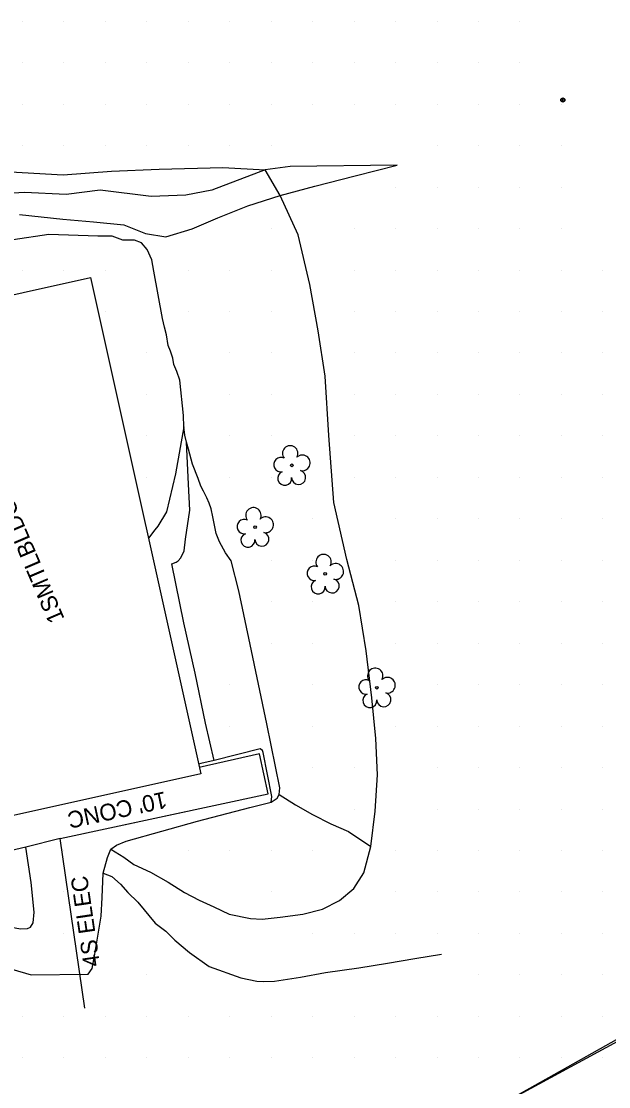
# Model space of a CAD drawing. Extents: x 1548934 to 1561348, y 809680 to 824075.
# Drawn here: x 1551789.7 to 1551931.4, y 811053 to 811310 of the extents above; entities that cross this region are included whole.
import ezdxf

# ---------------------------------------------------------------- set-up
doc = ezdxf.new("R2010")
doc.units = 0
for name, color, linetype in [('Default', 7, 'Continuous'), ('Exist Building', 7, 'Continuous'), ('Exist Building Foundations Text', 7, 'Continuous'), ('Exist DTM QL2 LIDAR Elevation Point', 7, 'Continuous'), ('Exist Other Culture Area Outline', 7, 'Continuous'), ('Exist Other Culture Area Outline Text', 7, 'Continuous'), ('Exist Other Culture Fence Line Text', 7, 'Continuous'), ('Exist Roads Soil', 7, 'Continuous'), ('Exist Vegetation Tree CELL', 7, 'Continuous'), ('Exist Vegetation Woods Line', 7, 'Continuous'), ('P_RDY_Dimension_Text', 7, 'Continuous'), ('PH Exist DTM Breakline', 7, 'Continuous')]:
    doc.layers.add(name, color=color, linetype=linetype)

# ---------------------------------------------------------------- blocks, each defined once
blk = doc.blocks.new('SurveyPointCell')
at = {"layer": 'Default'}
for p, q in [((-0.5, 0), (0.5, 0)), ((0, -0.5), (0, 0.5))]:
    blk.add_line(p, q, dxfattribs=at)
blk.add_circle((0, 0), 0.5, dxfattribs=at)

msp = doc.modelspace()

# ---------------------------------------------------------------- linework, layer by layer
at = {"layer": 'Exist Building'}
msp.add_lwpolyline([(1551783.41, 811117.5), (1551756.83, 811237.21), (1551806.41, 811248.22), (1551832.98, 811128.51)], close=True, dxfattribs=at)
at = {"layer": 'Exist DTM QL2 LIDAR Elevation Point'}
for p, q in [((1551790, 811310.04), (1551790, 811310.04)), ((1551800, 811310.04), (1551800, 811310.04)), ((1551810, 811310.04), (1551810, 811310.04)), ((1551820, 811310.04), (1551820, 811310.04)), ((1551830.01, 811310.04), (1551830.01, 811310.04)), ((1551840.01, 811310.04), (1551840.01, 811310.04)), ((1551850.01, 811310.04), (1551850.01, 811310.04)), ((1551860.01, 811310.04), (1551860.01, 811310.04)), ((1551870.01, 811310.04), (1551870.01, 811310.04)), ((1551880.01, 811310.04), (1551880.01, 811310.04)), ((1551890.01, 811310.04), (1551890.01, 811310.04)), ((1551900.01, 811310.04), (1551900.01, 811310.04)), ((1551910.01, 811310.04), (1551910.01, 811310.04)), ((1551790, 811300.03), (1551790, 811300.03)), ((1551800, 811300.03), (1551800, 811300.03)), ((1551810, 811300.03), (1551810, 811300.03)), ((1551820, 811300.03), (1551820, 811300.03)), ((1551830.01, 811300.03), (1551830.01, 811300.03)), ((1551840.01, 811300.03), (1551840.01, 811300.03)), ((1551850.01, 811300.03), (1551850.01, 811300.03)), ((1551860.01, 811300.03), (1551860.01, 811300.03)), ((1551870.01, 811300.03), (1551870.01, 811300.03)), ((1551880.01, 811300.03), (1551880.01, 811300.03)), ((1551890.01, 811300.03), (1551890.01, 811300.03)), ((1551900.01, 811300.03), (1551900.01, 811300.03)), ((1551910.01, 811300.03), (1551910.01, 811300.03)), ((1551790, 811290.03), (1551790, 811290.03)), ((1551800, 811290.03), (1551800, 811290.03)), ((1551810, 811290.03), (1551810, 811290.03)), ((1551820, 811290.03), (1551820, 811290.03)), ((1551830.01, 811290.03), (1551830.01, 811290.03)), ((1551840.01, 811290.03), (1551840.01, 811290.03)), ((1551850.01, 811290.03), (1551850.01, 811290.03)), ((1551860.01, 811290.03), (1551860.01, 811290.03)), ((1551870.01, 811290.03), (1551870.01, 811290.03)), ((1551880.01, 811290.03), (1551880.01, 811290.03)), ((1551890.01, 811290.03), (1551890.01, 811290.03)), ((1551900.01, 811290.03), (1551900.01, 811290.03)), ((1551910.01, 811290.03), (1551910.01, 811290.03)), ((1551920.01, 811290.03), (1551920.01, 811290.03)), ((1551790, 811280.03), (1551790, 811280.03)), ((1551800, 811280.03), (1551800, 811280.03)), ((1551810, 811280.03), (1551810, 811280.03)), ((1551820, 811280.03), (1551820, 811280.03)), ((1551830.01, 811280.03), (1551830.01, 811280.03)), ((1551840.01, 811280.03), (1551840.01, 811280.03)), ((1551850.01, 811280.03), (1551850.01, 811280.03)), ((1551890.01, 811280.03), (1551890.01, 811280.03)), ((1551900.01, 811280.03), (1551900.01, 811280.03)), ((1551910.01, 811280.03), (1551910.01, 811280.03)), ((1551920.01, 811280.03), (1551920.01, 811280.03)), ((1551880.01, 811270.03), (1551880.01, 811270.03)), ((1551890.01, 811270.03), (1551890.01, 811270.03)), ((1551900.01, 811270.03), (1551900.01, 811270.03)), ((1551910.01, 811270.03), (1551910.01, 811270.03)), ((1551920.01, 811270.03), (1551920.01, 811270.03)), ((1551850.01, 811260.03), (1551850.01, 811260.03)), ((1551870.01, 811260.03), (1551870.01, 811260.03)), ((1551880.01, 811260.03), (1551880.01, 811260.03)), ((1551890.01, 811260.03), (1551890.01, 811260.03)), ((1551900.01, 811260.03), (1551900.01, 811260.03)), ((1551910.01, 811260.03), (1551910.01, 811260.03)), ((1551920.01, 811260.03), (1551920.01, 811260.03)), ((1551790, 811250.03), (1551790, 811250.03)), ((1551800, 811250.03), (1551800, 811250.03)), ((1551810, 811250.03), (1551810, 811250.03)), ((1551830.01, 811250.03), (1551830.01, 811250.03)), ((1551840.01, 811250.03), (1551840.01, 811250.03)), ((1551850.01, 811250.03), (1551850.01, 811250.03)), ((1551870.01, 811250.03), (1551870.01, 811250.03)), ((1551880.01, 811250.03), (1551880.01, 811250.03)), ((1551890.01, 811250.03), (1551890.01, 811250.03)), ((1551900.01, 811250.03), (1551900.01, 811250.03)), ((1551910.01, 811250.03), (1551910.01, 811250.03)), ((1551920.01, 811250.03), (1551920.01, 811250.03)), ((1551930.01, 811250.03), (1551930.01, 811250.03)), ((1551810, 811240.03), (1551810, 811240.03)), ((1551830.01, 811240.03), (1551830.01, 811240.03)), ((1551840.01, 811240.03), (1551840.01, 811240.03)), ((1551850.01, 811240.03), (1551850.01, 811240.03)), ((1551870.01, 811240.03), (1551870.01, 811240.03)), ((1551880.01, 811240.03), (1551880.01, 811240.03)), ((1551890.01, 811240.03), (1551890.01, 811240.03)), ((1551900.01, 811240.03), (1551900.01, 811240.03)), ((1551910.01, 811240.03), (1551910.01, 811240.03)), ((1551920.01, 811240.03), (1551920.01, 811240.03)), ((1551930.01, 811240.03), (1551930.01, 811240.03)), ((1551820, 811230.03), (1551820, 811230.03)), ((1551840.01, 811230.03), (1551840.01, 811230.03)), ((1551850.01, 811230.03), (1551850.01, 811230.03)), ((1551870.01, 811230.03), (1551870.01, 811230.03)), ((1551880.01, 811230.03), (1551880.01, 811230.03)), ((1551890.01, 811230.03), (1551890.01, 811230.03)), ((1551900.01, 811230.03), (1551900.01, 811230.03)), ((1551910.01, 811230.03), (1551910.01, 811230.03)), ((1551920.01, 811230.03), (1551920.01, 811230.03)), ((1551930.01, 811230.03), (1551930.01, 811230.03)), ((1551820, 811220.03), (1551820, 811220.03)), ((1551840.01, 811220.03), (1551840.01, 811220.03)), ((1551850.01, 811220.03), (1551850.01, 811220.03)), ((1551870.01, 811220.03), (1551870.01, 811220.03)), ((1551880.01, 811220.03), (1551880.01, 811220.03)), ((1551890.01, 811220.03), (1551890.01, 811220.03)), ((1551900.01, 811220.03), (1551900.01, 811220.03)), ((1551910.01, 811220.03), (1551910.01, 811220.03)), ((1551920.01, 811220.03), (1551920.01, 811220.03)), ((1551930.01, 811220.03), (1551930.01, 811220.03)), ((1551820, 811210.03), (1551820, 811210.03)), ((1551840.01, 811210.03), (1551840.01, 811210.03)), ((1551850.01, 811210.03), (1551850.01, 811210.03)), ((1551870.01, 811210.03), (1551870.01, 811210.03)), ((1551880.01, 811210.03), (1551880.01, 811210.03)), ((1551890.01, 811210.03), (1551890.01, 811210.03)), ((1551900.01, 811210.03), (1551900.01, 811210.03)), ((1551910.01, 811210.03), (1551910.01, 811210.03)), ((1551920.01, 811210.03), (1551920.01, 811210.03)), ((1551930.01, 811210.03), (1551930.01, 811210.03)), ((1551820, 811200.03), (1551820, 811200.03)), ((1551840.01, 811200.03), (1551840.01, 811200.03)), ((1551850.01, 811200.03), (1551850.01, 811200.03)), ((1551870.01, 811200.03), (1551870.01, 811200.03)), ((1551880.01, 811200.03), (1551880.01, 811200.03)), ((1551890.01, 811200.03), (1551890.01, 811200.03)), ((1551900.01, 811200.03), (1551900.01, 811200.03)), ((1551910.01, 811200.03), (1551910.01, 811200.03)), ((1551920.01, 811200.03), (1551920.01, 811200.03)), ((1551930.01, 811200.03), (1551930.01, 811200.03)), ((1551850.01, 811190.03), (1551850.01, 811190.03)), ((1551860.01, 811190.03), (1551860.01, 811190.03)), ((1551880.01, 811190.03), (1551880.01, 811190.03)), ((1551890.01, 811190.03), (1551890.01, 811190.03)), ((1551900.01, 811190.03), (1551900.01, 811190.03)), ((1551910.01, 811190.03), (1551910.01, 811190.03)), ((1551920.01, 811190.03), (1551920.01, 811190.03)), ((1551930.01, 811190.03), (1551930.01, 811190.03)), ((1551850.01, 811180.03), (1551850.01, 811180.03)), ((1551860.01, 811180.03), (1551860.01, 811180.03)), ((1551880.01, 811180.03), (1551880.01, 811180.03)), ((1551890.01, 811180.03), (1551890.01, 811180.03)), ((1551900.01, 811180.03), (1551900.01, 811180.03)), ((1551910.01, 811180.03), (1551910.01, 811180.03)), ((1551920.01, 811180.03), (1551920.01, 811180.03)), ((1551930.01, 811180.03), (1551930.01, 811180.03)), ((1551850.01, 811170.02), (1551850.01, 811170.02)), ((1551860.01, 811170.02), (1551860.01, 811170.02)), ((1551880.01, 811170.02), (1551880.01, 811170.02)), ((1551890.01, 811170.02), (1551890.01, 811170.02)), ((1551900.01, 811170.02), (1551900.01, 811170.02)), ((1551910.01, 811170.02), (1551910.01, 811170.02)), ((1551920.01, 811170.02), (1551920.01, 811170.02)), ((1551930.01, 811170.02), (1551930.01, 811170.02)), ((1551850.01, 811160.02), (1551850.01, 811160.02)), ((1551860.01, 811160.02), (1551860.01, 811160.02)), ((1551880.01, 811160.02), (1551880.01, 811160.02)), ((1551890.01, 811160.02), (1551890.01, 811160.02)), ((1551900.01, 811160.02), (1551900.01, 811160.02)), ((1551910.01, 811160.02), (1551910.01, 811160.02)), ((1551920.01, 811160.02), (1551920.01, 811160.02)), ((1551930.01, 811160.02), (1551930.01, 811160.02)), ((1551840.01, 811150.02), (1551840.01, 811150.02)), ((1551860.01, 811150.02), (1551860.01, 811150.02)), ((1551880.01, 811150.02), (1551880.01, 811150.02)), ((1551890.01, 811150.02), (1551890.01, 811150.02)), ((1551900.01, 811150.02), (1551900.01, 811150.02)), ((1551910.01, 811150.02), (1551910.01, 811150.02)), ((1551920.01, 811150.02), (1551920.01, 811150.02)), ((1551930.01, 811150.02), (1551930.01, 811150.02)), ((1551840.01, 811140.02), (1551840.01, 811140.02)), ((1551860.01, 811140.02), (1551860.01, 811140.02)), ((1551880.01, 811140.02), (1551880.01, 811140.02)), ((1551890.01, 811140.02), (1551890.01, 811140.02)), ((1551900.01, 811140.02), (1551900.01, 811140.02)), ((1551910.01, 811140.02), (1551910.01, 811140.02)), ((1551920.01, 811140.02), (1551920.01, 811140.02)), ((1551930.01, 811140.02), (1551930.01, 811140.02)), ((1551860.01, 811130.02), (1551860.01, 811130.02)), ((1551870.01, 811130.02), (1551870.01, 811130.02)), ((1551890.01, 811130.02), (1551890.01, 811130.02)), ((1551900.01, 811130.02), (1551900.01, 811130.02)), ((1551910.01, 811130.02), (1551910.01, 811130.02)), ((1551920.01, 811130.02), (1551920.01, 811130.02)), ((1551930.01, 811130.02), (1551930.01, 811130.02)), ((1551810, 811120.02), (1551810, 811120.02)), ((1551870.01, 811120.02), (1551870.01, 811120.02)), ((1551890.01, 811120.02), (1551890.01, 811120.02)), ((1551900.01, 811120.02), (1551900.01, 811120.02)), ((1551910.01, 811120.02), (1551910.01, 811120.02)), ((1551920.01, 811120.02), (1551920.01, 811120.02)), ((1551930.01, 811120.02), (1551930.01, 811120.02)), ((1551800, 811110.02), (1551800, 811110.02)), ((1551830.01, 811110.02), (1551830.01, 811110.02)), ((1551840.01, 811110.02), (1551840.01, 811110.02)), ((1551850.01, 811110.02), (1551850.01, 811110.02)), ((1551860.01, 811110.02), (1551860.01, 811110.02)), ((1551880.01, 811110.02), (1551880.01, 811110.02)), ((1551890.01, 811110.02), (1551890.01, 811110.02)), ((1551900.01, 811110.02), (1551900.01, 811110.02)), ((1551910.01, 811110.02), (1551910.01, 811110.02)), ((1551920.01, 811110.02), (1551920.01, 811110.02)), ((1551930.01, 811110.02), (1551930.01, 811110.02)), ((1551800, 811100.02), (1551800, 811100.02)), ((1551850.01, 811100.02), (1551850.01, 811100.02)), ((1551880.01, 811100.02), (1551880.01, 811100.02)), ((1551890.01, 811100.02), (1551890.01, 811100.02)), ((1551900.01, 811100.02), (1551900.01, 811100.02)), ((1551910.01, 811100.02), (1551910.01, 811100.02)), ((1551920.01, 811100.02), (1551920.01, 811100.02)), ((1551930.01, 811100.02), (1551930.01, 811100.02)), ((1551800, 811090.02), (1551800, 811090.02)), ((1551860.01, 811090.02), (1551860.01, 811090.02)), ((1551870.01, 811090.02), (1551870.01, 811090.02)), ((1551880.01, 811090.02), (1551880.01, 811090.02)), ((1551890.01, 811090.02), (1551890.01, 811090.02)), ((1551900.01, 811090.02), (1551900.01, 811090.02)), ((1551910.01, 811090.02), (1551910.01, 811090.02)), ((1551920.01, 811090.02), (1551920.01, 811090.02)), ((1551930.01, 811090.02), (1551930.01, 811090.02)), ((1551820, 811080.02), (1551820, 811080.02)), ((1551900.01, 811080.02), (1551900.01, 811080.02)), ((1551910.01, 811080.02), (1551910.01, 811080.02)), ((1551920.01, 811080.02), (1551920.01, 811080.02)), ((1551930.01, 811080.02), (1551930.01, 811080.02)), ((1551790, 811070.02), (1551790, 811070.02)), ((1551800, 811070.02), (1551800, 811070.02)), ((1551810, 811070.02), (1551810, 811070.02)), ((1551820, 811070.02), (1551820, 811070.02)), ((1551830.01, 811070.02), (1551830.01, 811070.02)), ((1551840.01, 811070.02), (1551840.01, 811070.02)), ((1551850.01, 811070.02), (1551850.01, 811070.02)), ((1551860.01, 811070.02), (1551860.01, 811070.02)), ((1551870.01, 811070.02), (1551870.01, 811070.02)), ((1551880.01, 811070.02), (1551880.01, 811070.02)), ((1551890.01, 811070.02), (1551890.01, 811070.02)), ((1551900.01, 811070.02), (1551900.01, 811070.02)), ((1551910.01, 811070.02), (1551910.01, 811070.02)), ((1551920.01, 811070.02), (1551920.01, 811070.02)), ((1551930.01, 811070.02), (1551930.01, 811070.02)), ((1551790, 811060.02), (1551790, 811060.02)), ((1551800, 811060.02), (1551800, 811060.02)), ((1551810, 811060.02), (1551810, 811060.02)), ((1551820, 811060.02), (1551820, 811060.02)), ((1551830.01, 811060.02), (1551830.01, 811060.02)), ((1551840.01, 811060.02), (1551840.01, 811060.02)), ((1551850.01, 811060.02), (1551850.01, 811060.02)), ((1551860.01, 811060.02), (1551860.01, 811060.02)), ((1551870.01, 811060.02), (1551870.01, 811060.02)), ((1551880.01, 811060.02), (1551880.01, 811060.02)), ((1551890.01, 811060.02), (1551890.01, 811060.02)), ((1551900.01, 811060.02), (1551900.01, 811060.02)), ((1551910.01, 811060.02), (1551910.01, 811060.02)), ((1551920.01, 811060.02), (1551920.01, 811060.02)), ((1551930.01, 811060.02), (1551930.01, 811060.02))]:
    msp.add_line(p, q, dxfattribs=at)
at = {"layer": 'Exist Other Culture Area Outline'}
for points in [[(1551799.11, 811112.91), (1551790.77, 811110.81), (1551781.78, 811108.69), (1551779.56, 811117.98), (1551770.71, 811158.5), (1551762.17, 811196.63), (1551765.67, 811197.39)], [(1551799.11, 811112.91), (1551849.29, 811123.67), (1551847.19, 811133.35), (1551832.65, 811130)]]:
    msp.add_lwpolyline(points, dxfattribs=at)
at = {"layer": 'Exist Roads Soil'}
msp.add_lwpolyline([(1551719.47, 811081.25), (1551723.96, 811090.53), (1551725.4, 811092.26), (1551726.5, 811093.32), (1551728.63, 811094.38), (1551731.91, 811095.85), (1551735.51, 811097.03), (1551740.14, 811098.04), (1551753.48, 811098.66), (1551765.04, 811098.05), (1551777.83, 811094.69), (1551785.62, 811091.88), (1551789.5, 811091.12), (1551791.17, 811091.18), (1551791.89, 811091.54), (1551792.56, 811092.56), (1551792.81, 811095.13), (1551792.06, 811102.27), (1551790.77, 811110.81)], dxfattribs=at)
at = {"layer": 'Exist Vegetation Tree CELL'}
for p, q in [((1551854.95, 811202.93), (1551854.95, 811202.93)), ((1551846.09, 811187.99), (1551846.09, 811187.99)), ((1551863.01, 811176.73), (1551863.01, 811176.73)), ((1551875.49, 811149.29), (1551875.49, 811149.29))]:
    msp.add_line(p, q, dxfattribs=at)
for centre in [(1551854.95, 811202.93), (1551846.09, 811187.99), (1551863.01, 811176.73), (1551875.49, 811149.29)]:
    msp.add_circle(centre, 0.326, dxfattribs=at)
for centre, radius, start, end in [((1551854.57, 811205.81), 1.86, 330.1651, 219.7134), ((1551857.5, 811203.52), 1.9, 257.1011, 134.1999), ((1551852.35, 811203.09), 1.73, 62.6636, 279.3457), ((1551853.25, 811199.81), 1.69, 111.5671, 6.231), ((1551856.63, 811200.03), 1.7, 181.2822, 74.56), ((1551845.7, 811190.87), 1.86, 330.1651, 219.7134), ((1551843.48, 811188.15), 1.73, 62.6636, 279.3457), ((1551848.64, 811188.58), 1.9, 257.1011, 134.1999), ((1551844.38, 811184.87), 1.69, 111.5671, 6.231), ((1551847.76, 811185.1), 1.7, 181.2822, 74.56), ((1551862.63, 811179.6), 1.86, 330.1651, 219.7134), ((1551860.41, 811176.88), 1.73, 62.6636, 279.3457), ((1551865.56, 811177.32), 1.9, 257.1011, 134.1999), ((1551861.31, 811173.61), 1.69, 111.5671, 6.231), ((1551864.69, 811173.83), 1.7, 181.2822, 74.56), ((1551875.1, 811152.16), 1.86, 330.1651, 219.7134), ((1551872.88, 811149.44), 1.73, 62.6636, 279.3457), ((1551878.04, 811149.88), 1.9, 257.1011, 134.1999), ((1551873.78, 811146.17), 1.69, 111.5671, 6.231), ((1551877.16, 811146.39), 1.7, 181.2822, 74.56)]:
    msp.add_arc(centre, radius, start, end, dxfattribs=at)
at = {"layer": 'Exist Vegetation Woods Line'}
msp.add_lwpolyline([(1551977.93, 810998.3), (1551970.88, 810994.36), (1551960.15, 810989.16), (1551950.01, 810984.47), (1551942.26, 810982.58), (1551935.79, 810981.88), (1551927.04, 810985.6), (1551917.17, 810997.94), (1551912.39, 811001.64), (1551905.64, 811006.2), (1551898.94, 811010.16), (1551894.03, 811013.82), (1551889.51, 811019.9), (1551884.86, 811024.1), (1551880.67, 811028.77), (1551884.61, 811037.75), (1551893.7, 811042.39), (1551949.83, 811072.75)], dxfattribs=at)
at = {"layer": 'P_RDY_Dimension_Text'}
for p, q in [((1551799.11, 811112.91), (1551829.41, 811119.41)), ((1551805.05, 811072.01), (1551799.11, 811112.91))]:
    msp.add_line(p, q, dxfattribs=at)
msp.add_lwpolyline([(1551792.63, 810879.89), (1551798.87, 810886.61), (1551791.81, 810954.68), (1551790.16, 810983.57), (1551796.35, 810987.52), (1551966.16, 811082.82)], dxfattribs=at)
at = {"layer": 'PH Exist DTM Breakline'}
for points in [[(1551747.3, 811271.49), (1551764.33, 811274.15), (1551774.85, 811274.24), (1551787.12, 811273.73), (1551799.76, 811272.99), (1551811.5, 811273.85), (1551823, 811274.34), (1551838.34, 811274.74), (1551848.51, 811274.21)], [(1551789.25, 811263.41), (1551799.7, 811262.28), (1551807.09, 811261.64), (1551814.44, 811260.93), (1551819.66, 811258.84), (1551824.57, 811258.06), (1551830.89, 811259.94), (1551837.14, 811262.65), (1551844.38, 811265.55), (1551852.19, 811268.01), (1551860.5, 811270.23), (1551870.25, 811272.79), (1551880.35, 811275.34), (1551854.57, 811275.02), (1551848.51, 811274.21), (1551835.63, 811269.31), (1551829.37, 811268.08), (1551821.04, 811267.76), (1551808.69, 811269.3), (1551800.53, 811268.26), (1551790.45, 811268.75), (1551780.94, 811268.16)], [(1551811.34, 811110.37), (1551814.41, 811108.41), (1551816.87, 811106.61), (1551820.87, 811104.79), (1551825.14, 811102.38), (1551829.05, 811099.91), (1551832.58, 811098.05), (1551836.19, 811096.46), (1551839.83, 811094.67), (1551844.96, 811093.62), (1551847.78, 811093.47), (1551852.17, 811093.93), (1551857.64, 811094.64), (1551862.37, 811095.89), (1551866.47, 811097.97), (1551869.9, 811100.87), (1551872.35, 811104.65), (1551874.05, 811111.01), (1551875.04, 811119.54), (1551875.66, 811128.29), (1551875.2, 811137.06), (1551874.26, 811146.81), (1551872.9, 811158.14), (1551871.15, 811169.15), (1551868.23, 811180.19), (1551865.12, 811193.93), (1551863.91, 811210.15), (1551863.02, 811224.4), (1551861.34, 811235.38), (1551859.3, 811246.54), (1551856.48, 811258.53), (1551852.19, 811268.01), (1551848.51, 811274.21)], [(1551784.06, 811082.39), (1551792.04, 811080.05), (1551805.86, 811080.15), (1551806.78, 811081.58), (1551807.42, 811085.04), (1551808.93, 811094.21), (1551809.23, 811098.67), (1551809.47, 811104.53), (1551810.49, 811108.32), (1551811.34, 811110.37), (1551812.64, 811111.31), (1551814.99, 811112.25), (1551832.25, 811117.11), (1551844.85, 811120.37), (1551849.95, 811121.7), (1551851.4, 811122.61), (1551851.92, 811123.56), (1551852.09, 811125.1), (1551848.98, 811140.57), (1551844.89, 811159.71), (1551842.15, 811172.63), (1551840.36, 811179.9), (1551838.94, 811181.8), (1551837.53, 811184.48), (1551836.71, 811186.45), (1551835.9, 811190.47), (1551835.5, 811192.44), (1551835.03, 811193.83), (1551834.45, 811195.11), (1551833.62, 811196.72), (1551833, 811197.92), (1551832.37, 811199.74), (1551831.04, 811203.22), (1551830.02, 811206.81), (1551829.58, 811208.49), (1551829.15, 811210.18), (1551828.94, 811212.22), (1551828.86, 811214.93), (1551827.97, 811223.49), (1551827.19, 811225.54), (1551826.53, 811227.29), (1551826.3, 811228.76), (1551825.66, 811230.44), (1551825.12, 811231.8), (1551824.72, 811234.41), (1551824.22, 811236.28), (1551823.8, 811238.31), (1551821.65, 811249.75), (1551821.21, 811252.48), (1551820.07, 811254.97), (1551818.67, 811256.6), (1551816.98, 811257.22), (1551814.22, 811257.26), (1551811.65, 811258.21), (1551808.13, 811258.2), (1551796.38, 811258.61), (1551787.74, 811257.34)], [(1551828.94, 811212.22), (1551826.88, 811200.91), (1551824.74, 811191.67), (1551822.66, 811188.23), (1551821.93, 811187.4), (1551820.37, 811185.34)], [(1551836.21, 811131.7), (1551834.14, 811140.72), (1551831.65, 811152.82), (1551828.95, 811164.95), (1551826, 811179.19), (1551827.09, 811179.59), (1551827.57, 811179.92), (1551828.18, 811180.61), (1551829.02, 811182.31), (1551829.35, 811185.1), (1551830.38, 811192.09), (1551830.02, 811198.42), (1551829.58, 811208.49)], [(1551849.95, 811121.7), (1551850.13, 811123.04), (1551848.09, 811133.69), (1551847.88, 811134.15), (1551847.34, 811134.5), (1551836.21, 811131.7), (1551833.03, 811130.98), (1551832.46, 811130.87)], [(1551851.92, 811123.56), (1551855.85, 811121.04), (1551859.97, 811118.7), (1551864.41, 811116.48), (1551868.62, 811114.61), (1551874.05, 811111.01)], [(1551809.47, 811104.53), (1551811.55, 811103.74), (1551813.61, 811101.92), (1551815.43, 811099.92), (1551817.84, 811097.55), (1551822, 811092.48), (1551824.55, 811090.52), (1551826.77, 811088.4), (1551830.3, 811085.45), (1551835, 811082.01), (1551842.68, 811079.31), (1551846.5, 811078.53), (1551848.23, 811078.41), (1551850.77, 811078.48), (1551857.08, 811079.49), (1551863.06, 811080.62), (1551871.15, 811081.73), (1551878.09, 811082.82), (1551884.62, 811083.95), (1551891.06, 811084.99)]]:
    msp.add_lwpolyline(points, dxfattribs=at)

# ---------------------------------------------------------------- block references
at = {"layer": 'Default'}
msp.add_blockref('SurveyPointCell', (1551920.36, 811291.06), dxfattribs=at)

# ---------------------------------------------------------------- texts
at = {"layer": 'Exist Building Foundations Text'}
msp.add_text('1SMTLBLDG', height=4.02, rotation=113.1852, dxfattribs=at).set_placement((1551800.19, 811165.93))
at = {"layer": 'Exist Other Culture Area Outline Text'}
msp.add_text("10' CONC", height=4.02, rotation=192.1092, dxfattribs=at).set_placement((1551824.33, 811124.3))
at = {"layer": 'Exist Other Culture Fence Line Text'}
msp.add_text('4S ELEC', height=4.02, rotation=98.2653, dxfattribs=at).set_placement((1551808.75, 811082.24))

doc.saveas('drawing.dxf')
